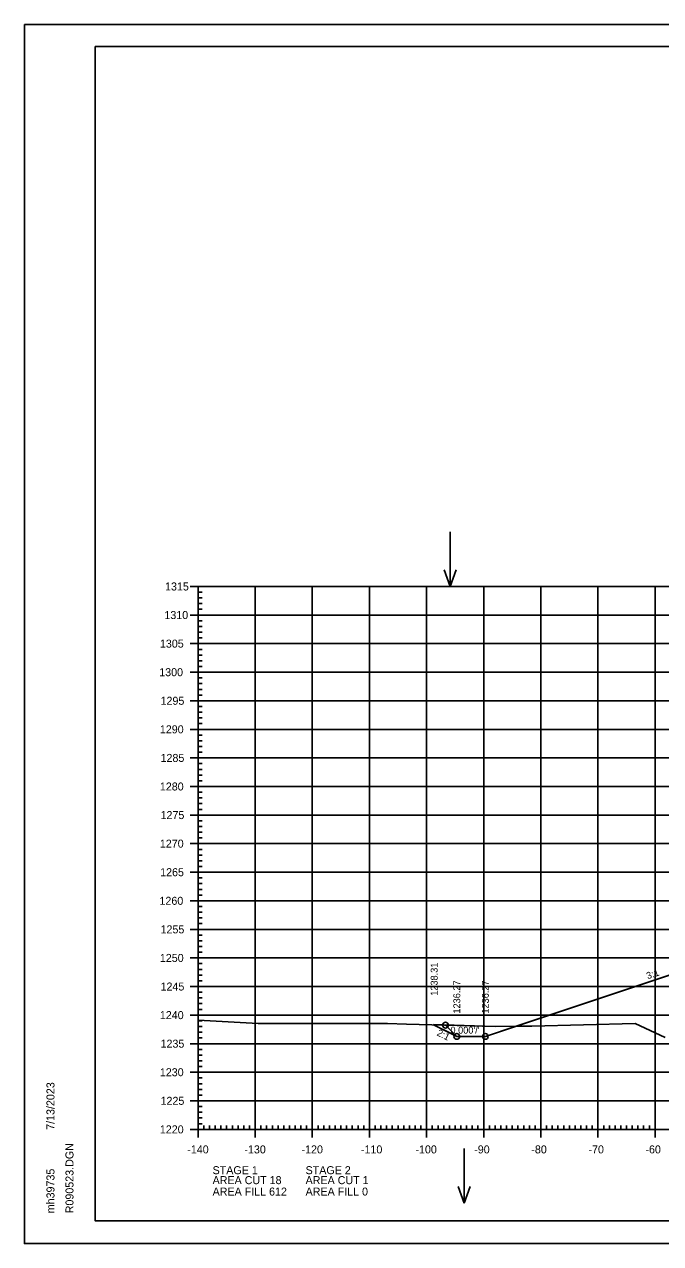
# Model space of a CAD drawing. Extents: x 1406028 to 1412453, y 321733 to 325986.
# Drawn here: x 1406419.5 to 1406530.9, y 324492.7 to 324706.1 of the extents above; entities that cross this region are included whole.
import ezdxf

# ---------------------------------------------------------------- set-up
doc = ezdxf.new("R2010")
doc.units = 0
for name, color, linetype in [('R_Axis', 7, 'Continuous'), ('R_Axis Annot', 7, 'Continuous'), ('R_Border', 7, 'Continuous'), ('R_Exist Surface', 7, 'Continuous'), ('R_Fin Surface', 7, 'Continuous'), ('R_Fin Surface Annot', 7, 'Continuous'), ('R_Grid', 7, 'Continuous'), ('R_No Plot', 7, 'Continuous'), ('R_Proposed Const Limits', 7, 'Continuous'), ('R_Proposed Road', 7, 'Continuous'), ('R_Water Annot', 7, 'Continuous')]:
    doc.layers.add(name, color=color, linetype=linetype)

msp = doc.modelspace()

# ---------------------------------------------------------------- linework, layer by layer
at = {"layer": 'R_Axis'}
for p, q in [((1406448.49, 324607.71), (1406451.29, 324607.71)), ((1406449.89, 324512.71), (1406449.89, 324607.71)), ((1406449.89, 324606.71), (1406450.59, 324606.71)), ((1406449.89, 324605.71), (1406450.59, 324605.71)), ((1406449.89, 324604.71), (1406450.59, 324604.71)), ((1406448.49, 324602.71), (1406451.29, 324602.71)), ((1406449.89, 324603.71), (1406450.59, 324603.71)), ((1406449.89, 324601.71), (1406450.59, 324601.71)), ((1406449.89, 324600.71), (1406450.59, 324600.71)), ((1406449.89, 324599.71), (1406450.59, 324599.71)), ((1406448.49, 324597.71), (1406451.29, 324597.71)), ((1406449.89, 324598.71), (1406450.59, 324598.71)), ((1406449.89, 324596.71), (1406450.59, 324596.71)), ((1406449.89, 324595.71), (1406450.59, 324595.71)), ((1406449.89, 324594.71), (1406450.59, 324594.71)), ((1406449.89, 324593.71), (1406450.59, 324593.71)), ((1406448.49, 324592.71), (1406451.29, 324592.71)), ((1406449.89, 324591.71), (1406450.59, 324591.71)), ((1406449.89, 324590.71), (1406450.59, 324590.71)), ((1406449.89, 324589.71), (1406450.59, 324589.71)), ((1406448.49, 324587.71), (1406451.29, 324587.71)), ((1406449.89, 324588.71), (1406450.59, 324588.71)), ((1406449.89, 324586.71), (1406450.59, 324586.71)), ((1406449.89, 324585.71), (1406450.59, 324585.71)), ((1406449.89, 324584.71), (1406450.59, 324584.71)), ((1406448.49, 324582.71), (1406451.29, 324582.71)), ((1406449.89, 324583.71), (1406450.59, 324583.71)), ((1406449.89, 324581.71), (1406450.59, 324581.71)), ((1406449.89, 324580.71), (1406450.59, 324580.71)), ((1406449.89, 324579.71), (1406450.59, 324579.71)), ((1406449.89, 324578.71), (1406450.59, 324578.71)), ((1406448.49, 324577.71), (1406451.29, 324577.71)), ((1406449.89, 324576.71), (1406450.59, 324576.71)), ((1406449.89, 324575.71), (1406450.59, 324575.71)), ((1406449.89, 324574.71), (1406450.59, 324574.71)), ((1406448.49, 324572.71), (1406451.29, 324572.71)), ((1406449.89, 324573.71), (1406450.59, 324573.71)), ((1406449.89, 324571.71), (1406450.59, 324571.71)), ((1406449.89, 324570.71), (1406450.59, 324570.71)), ((1406449.89, 324569.71), (1406450.59, 324569.71)), ((1406448.49, 324567.71), (1406451.29, 324567.71)), ((1406449.89, 324568.71), (1406450.59, 324568.71)), ((1406449.89, 324566.71), (1406450.59, 324566.71)), ((1406449.89, 324565.71), (1406450.59, 324565.71)), ((1406449.89, 324564.71), (1406450.59, 324564.71)), ((1406449.89, 324563.71), (1406450.59, 324563.71)), ((1406448.49, 324562.71), (1406451.29, 324562.71)), ((1406449.89, 324561.71), (1406450.59, 324561.71)), ((1406449.89, 324560.71), (1406450.59, 324560.71)), ((1406449.89, 324559.71), (1406450.59, 324559.71)), ((1406448.49, 324557.71), (1406451.29, 324557.71)), ((1406449.89, 324558.71), (1406450.59, 324558.71)), ((1406449.89, 324556.71), (1406450.59, 324556.71)), ((1406449.89, 324555.71), (1406450.59, 324555.71)), ((1406448.49, 324552.71), (1406451.29, 324552.71)), ((1406449.89, 324554.71), (1406450.59, 324554.71)), ((1406449.89, 324553.71), (1406450.59, 324553.71)), ((1406449.89, 324551.71), (1406450.59, 324551.71)), ((1406449.89, 324550.71), (1406450.59, 324550.71)), ((1406449.89, 324549.71), (1406450.59, 324549.71)), ((1406449.89, 324548.71), (1406450.59, 324548.71)), ((1406448.49, 324547.71), (1406451.29, 324547.71)), ((1406449.89, 324546.71), (1406450.59, 324546.71)), ((1406449.89, 324545.71), (1406450.59, 324545.71)), ((1406449.89, 324544.71), (1406450.59, 324544.71)), ((1406448.49, 324542.71), (1406451.29, 324542.71)), ((1406449.89, 324543.71), (1406450.59, 324543.71)), ((1406449.89, 324541.71), (1406450.59, 324541.71)), ((1406449.89, 324540.71), (1406450.59, 324540.71)), ((1406448.49, 324537.71), (1406451.29, 324537.71)), ((1406449.89, 324539.71), (1406450.59, 324539.71)), ((1406449.89, 324538.71), (1406450.59, 324538.71)), ((1406449.89, 324536.71), (1406450.59, 324536.71)), ((1406449.89, 324535.71), (1406450.59, 324535.71)), ((1406449.89, 324534.71), (1406450.59, 324534.71)), ((1406449.89, 324533.71), (1406450.59, 324533.71)), ((1406448.49, 324532.71), (1406451.29, 324532.71)), ((1406449.89, 324531.71), (1406450.59, 324531.71)), ((1406449.89, 324530.71), (1406450.59, 324530.71)), ((1406449.89, 324529.71), (1406450.59, 324529.71)), ((1406448.49, 324527.71), (1406451.29, 324527.71)), ((1406449.89, 324528.71), (1406450.59, 324528.71)), ((1406449.89, 324526.71), (1406450.59, 324526.71)), ((1406449.89, 324525.71), (1406450.59, 324525.71)), ((1406449.89, 324524.71), (1406450.59, 324524.71)), ((1406449.89, 324523.71), (1406450.59, 324523.71)), ((1406448.49, 324522.71), (1406451.29, 324522.71)), ((1406449.89, 324521.71), (1406450.59, 324521.71)), ((1406449.89, 324520.71), (1406450.59, 324520.71)), ((1406449.89, 324519.71), (1406450.59, 324519.71)), ((1406449.89, 324518.71), (1406450.59, 324518.71)), ((1406448.49, 324517.71), (1406451.29, 324517.71)), ((1406449.89, 324516.71), (1406450.59, 324516.71)), ((1406449.89, 324515.71), (1406450.59, 324515.71)), ((1406449.89, 324514.71), (1406450.59, 324514.71)), ((1406448.49, 324512.71), (1406451.29, 324512.71)), ((1406449.89, 324511.31), (1406449.89, 324514.11)), ((1406449.89, 324513.71), (1406450.59, 324513.71)), ((1406449.89, 324512.71), (1406729.89, 324512.71)), ((1406450.89, 324512.71), (1406450.89, 324513.41)), ((1406451.89, 324512.71), (1406451.89, 324513.41)), ((1406452.89, 324512.71), (1406452.89, 324513.41)), ((1406453.89, 324512.71), (1406453.89, 324513.41)), ((1406454.89, 324512.71), (1406454.89, 324513.41)), ((1406455.89, 324512.71), (1406455.89, 324513.41)), ((1406456.89, 324512.71), (1406456.89, 324513.41)), ((1406457.89, 324512.71), (1406457.89, 324513.41)), ((1406458.89, 324512.71), (1406458.89, 324513.41)), ((1406459.89, 324511.31), (1406459.89, 324514.11)), ((1406460.89, 324512.71), (1406460.89, 324513.41)), ((1406461.89, 324512.71), (1406461.89, 324513.41)), ((1406462.89, 324512.71), (1406462.89, 324513.41)), ((1406463.89, 324512.71), (1406463.89, 324513.41)), ((1406464.89, 324512.71), (1406464.89, 324513.41)), ((1406465.89, 324512.71), (1406465.89, 324513.41)), ((1406466.89, 324512.71), (1406466.89, 324513.41)), ((1406467.89, 324512.71), (1406467.89, 324513.41)), ((1406468.89, 324512.71), (1406468.89, 324513.41)), ((1406469.89, 324511.31), (1406469.89, 324514.11)), ((1406470.89, 324512.71), (1406470.89, 324513.41)), ((1406471.89, 324512.71), (1406471.89, 324513.41)), ((1406472.89, 324512.71), (1406472.89, 324513.41)), ((1406473.89, 324512.71), (1406473.89, 324513.41)), ((1406474.89, 324512.71), (1406474.89, 324513.41)), ((1406475.89, 324512.71), (1406475.89, 324513.41)), ((1406476.89, 324512.71), (1406476.89, 324513.41)), ((1406477.89, 324512.71), (1406477.89, 324513.41)), ((1406478.89, 324512.71), (1406478.89, 324513.41)), ((1406479.89, 324511.31), (1406479.89, 324514.11)), ((1406480.89, 324512.71), (1406480.89, 324513.41)), ((1406481.89, 324512.71), (1406481.89, 324513.41)), ((1406482.89, 324512.71), (1406482.89, 324513.41)), ((1406483.89, 324512.71), (1406483.89, 324513.41)), ((1406484.89, 324512.71), (1406484.89, 324513.41)), ((1406485.89, 324512.71), (1406485.89, 324513.41)), ((1406486.89, 324512.71), (1406486.89, 324513.41)), ((1406487.89, 324512.71), (1406487.89, 324513.41)), ((1406488.89, 324512.71), (1406488.89, 324513.41)), ((1406489.89, 324511.31), (1406489.89, 324514.11)), ((1406490.89, 324512.71), (1406490.89, 324513.41)), ((1406491.89, 324512.71), (1406491.89, 324513.41)), ((1406492.89, 324512.71), (1406492.89, 324513.41)), ((1406493.89, 324512.71), (1406493.89, 324513.41)), ((1406494.89, 324512.71), (1406494.89, 324513.41)), ((1406495.89, 324512.71), (1406495.89, 324513.41)), ((1406496.89, 324512.71), (1406496.89, 324513.41)), ((1406497.89, 324512.71), (1406497.89, 324513.41)), ((1406498.89, 324512.71), (1406498.89, 324513.41)), ((1406499.89, 324511.31), (1406499.89, 324514.11)), ((1406500.89, 324512.71), (1406500.89, 324513.41)), ((1406501.89, 324512.71), (1406501.89, 324513.41)), ((1406502.89, 324512.71), (1406502.89, 324513.41)), ((1406503.89, 324512.71), (1406503.89, 324513.41)), ((1406504.89, 324512.71), (1406504.89, 324513.41)), ((1406505.89, 324512.71), (1406505.89, 324513.41)), ((1406506.89, 324512.71), (1406506.89, 324513.41)), ((1406507.89, 324512.71), (1406507.89, 324513.41)), ((1406508.89, 324512.71), (1406508.89, 324513.41)), ((1406509.89, 324511.31), (1406509.89, 324514.11)), ((1406510.89, 324512.71), (1406510.89, 324513.41)), ((1406511.89, 324512.71), (1406511.89, 324513.41)), ((1406512.89, 324512.71), (1406512.89, 324513.41)), ((1406513.89, 324512.71), (1406513.89, 324513.41)), ((1406514.89, 324512.71), (1406514.89, 324513.41)), ((1406515.89, 324512.71), (1406515.89, 324513.41)), ((1406516.89, 324512.71), (1406516.89, 324513.41)), ((1406517.89, 324512.71), (1406517.89, 324513.41)), ((1406518.89, 324512.71), (1406518.89, 324513.41)), ((1406519.89, 324511.31), (1406519.89, 324514.11)), ((1406520.89, 324512.71), (1406520.89, 324513.41)), ((1406521.89, 324512.71), (1406521.89, 324513.41)), ((1406522.89, 324512.71), (1406522.89, 324513.41)), ((1406523.89, 324512.71), (1406523.89, 324513.41)), ((1406524.89, 324512.71), (1406524.89, 324513.41)), ((1406525.89, 324512.71), (1406525.89, 324513.41)), ((1406526.89, 324512.71), (1406526.89, 324513.41)), ((1406527.89, 324512.71), (1406527.89, 324513.41)), ((1406528.89, 324512.71), (1406528.89, 324513.41)), ((1406529.89, 324511.31), (1406529.89, 324514.11))]:
    msp.add_line(p, q, dxfattribs=at)
at = {"layer": 'R_Border'}
for p, q in [((1406431.89, 324702.17), (1406748.07, 324702.17)), ((1406431.89, 324496.71), (1406431.89, 324702.17)), ((1406431.89, 324496.71), (1406431.89, 324496.71)), ((1406748.07, 324496.71), (1406431.89, 324496.71))]:
    msp.add_line(p, q, dxfattribs=at)
at = {"layer": 'R_Exist Surface'}
msp.add_lwpolyline([(1406449.89, 324531.84), (1406460.42, 324531.22), (1406481.71, 324531.24), (1406483.06, 324531.24), (1406486.36, 324531.15), (1406501.88, 324530.7), (1406508.3, 324530.8), (1406526.38, 324531.23), (1406531.65, 324528.77)], dxfattribs=at)
at = {"layer": 'R_Fin Surface'}
msp.add_line((1406495.19, 324528.97), (1406491.11, 324531.01), dxfattribs=at)
msp.add_lwpolyline([(1406491.11, 324531.01), (1406494.49, 324529.32), (1406495.18, 324528.97), (1406498.92, 324528.97), (1406500.18, 324528.97), (1406545.18, 324543.97)], dxfattribs=at)
at = {"layer": 'R_Grid'}
for p, q in [((1406449.89, 324607.71), (1406729.89, 324607.71)), ((1406449.89, 324512.71), (1406449.89, 324607.71)), ((1406459.89, 324512.71), (1406459.89, 324607.71)), ((1406469.89, 324512.71), (1406469.89, 324607.71)), ((1406479.89, 324512.71), (1406479.89, 324607.71)), ((1406489.89, 324512.71), (1406489.89, 324607.71)), ((1406499.89, 324512.71), (1406499.89, 324607.71)), ((1406509.89, 324512.71), (1406509.89, 324607.71)), ((1406519.89, 324512.71), (1406519.89, 324607.71)), ((1406529.89, 324512.71), (1406529.89, 324607.71)), ((1406449.89, 324602.71), (1406729.89, 324602.71)), ((1406449.89, 324597.71), (1406729.89, 324597.71)), ((1406449.89, 324592.71), (1406729.89, 324592.71)), ((1406449.89, 324587.71), (1406729.89, 324587.71)), ((1406449.89, 324582.71), (1406729.89, 324582.71)), ((1406449.89, 324577.71), (1406729.89, 324577.71)), ((1406449.89, 324572.71), (1406729.89, 324572.71)), ((1406449.89, 324567.71), (1406729.89, 324567.71)), ((1406449.89, 324562.71), (1406729.89, 324562.71)), ((1406449.89, 324557.71), (1406729.89, 324557.71)), ((1406449.89, 324552.71), (1406729.89, 324552.71)), ((1406449.89, 324547.71), (1406729.89, 324547.71)), ((1406449.89, 324542.71), (1406729.89, 324542.71)), ((1406449.89, 324537.71), (1406729.89, 324537.71)), ((1406449.89, 324532.71), (1406729.89, 324532.71)), ((1406449.89, 324527.71), (1406729.89, 324527.71)), ((1406449.89, 324522.71), (1406729.89, 324522.71)), ((1406449.89, 324517.71), (1406729.89, 324517.71)), ((1406449.89, 324512.71), (1406729.89, 324512.71))]:
    msp.add_line(p, q, dxfattribs=at)
at = {"layer": 'R_No Plot'}
for p, q in [((1406419.49, 324706.06), (1406752.82, 324706.06)), ((1406419.49, 324492.73), (1406752.82, 324492.73))]:
    msp.add_line(p, q, dxfattribs=at)
for points in [[(1406419.48, 324706.06), (1406752.82, 324706.06), (1406752.82, 324492.72), (1406419.48, 324492.72)], [(1406665.81, 324702.17), (1406685.43, 324702.17), (1406685.43, 324692.29), (1406701.54, 324692.29), (1406724.74, 324692.29), (1406724.74, 324667.95), (1406748.07, 324667.95), (1406748.07, 324496.71), (1406431.89, 324496.71), (1406431.89, 324702.17)], [(1406491.11, 324531.01), (1406491.11, 324531.06), (1406501.88, 324530.7), (1406505.55, 324530.76), (1406500.19, 324528.97), (1406498.25, 324528.97), (1406495.2, 324528.97), (1406494.19, 324529.47)]]:
    msp.add_lwpolyline(points, close=True, dxfattribs=at)
msp.add_lwpolyline([(1406537.41, 324541.37), (1406505.55, 324530.76), (1406508.3, 324530.8), (1406526.38, 324531.23), (1406531.65, 324528.77)], dxfattribs=at)
for centre in [(1406493.2, 324530.95), (1406495.18, 324528.97), (1406500.18, 324528.97)]:
    msp.add_circle(centre, 0.5, dxfattribs=at)
at = {"layer": 'R_Proposed Const Limits'}
msp.add_lwpolyline([(1406500.18, 324528.97), (1406495.18, 324528.97), (1406493.2, 324530.95)], dxfattribs=at)
at = {"layer": 'R_Proposed Road'}
msp.add_lwpolyline([(1406559.89, 324548.88), (1406500.18, 324528.97)], dxfattribs=at)
at = {"layer": 'R_Water Annot'}
for p, q in [((1406494, 324617.28), (1406494, 324607.71)), ((1406494, 324607.71), (1406492.94, 324610.64)), ((1406494, 324607.71), (1406495.07, 324610.64)), ((1406496.46, 324509.36), (1406496.46, 324499.79)), ((1406496.46, 324499.79), (1406495.4, 324502.72)), ((1406496.46, 324499.79), (1406497.53, 324502.72))]:
    msp.add_line(p, q, dxfattribs=at)

# ---------------------------------------------------------------- texts
at = {"layer": 'R_Axis Annot'}
for s, p in [('1315', (1406444.11, 324607.01)), ('1310', (1406443.99, 324602.01)), ('1305', (1406443.21, 324597.01)), ('1300', (1406443.09, 324592.01)), ('1295', (1406443.32, 324587.01)), ('1290', (1406443.2, 324582.01)), ('1285', (1406443.32, 324577.01)), ('1280', (1406443.2, 324572.01)), ('1275', (1406443.32, 324567.01)), ('1270', (1406443.2, 324562.01)), ('1265', (1406443.25, 324557.01)), ('1260', (1406443.13, 324552.01)), ('1255', (1406443.32, 324547.01)), ('1250', (1406443.2, 324542.01)), ('1245', (1406443.32, 324537.01)), ('1240', (1406443.2, 324532.01)), ('1235', (1406443.32, 324527.01)), ('1230', (1406443.2, 324522.01)), ('1225', (1406443.32, 324517.01)), ('1220', (1406443.2, 324512.01)), ('-140', (1406448, 324508.51)), ('-130', (1406458, 324508.51)), ('-120', (1406468, 324508.51)), ('-110', (1406478.4, 324508.51)), ('-100', (1406487.94, 324508.51)), ('-90', (1406498.23, 324508.51)), ('-80', (1406508.23, 324508.51)), ('-70', (1406518.23, 324508.51)), ('-60', (1406528.2, 324508.51)), ('STAGE 1', (1406452.43, 324504.87)), ('STAGE 2', (1406468.71, 324504.87)), ('AREA CUT 18', (1406452.43, 324503.13)), ('AREA CUT 1', (1406468.71, 324503.13)), ('AREA FILL 612', (1406452.43, 324501.13)), ('AREA FILL 0', (1406468.71, 324501.13))]:
    msp.add_text(s, height=1.4, dxfattribs=at).set_placement(p)
at = {"layer": 'R_Border'}
for s, p in [('7/13/2023', (1406424.75, 324512.63)), ('R090523.DGN', (1406428.08, 324498.03)), ('mh39735', (1406424.75, 324498.03))]:
    msp.add_text(s, height=1.4, rotation=90, dxfattribs=at).set_placement(p)
at = {"layer": 'R_Fin Surface Annot'}
for s, rotation, p in [('1238.31', 90, (1406491.82, 324536.09)), ('3:1', 18.4333, (1406528.6, 324538.97)), ('1236.27', 90, (1406495.78, 324532.97)), ('1236.27', 90, (1406500.78, 324532.97)), ('2:1', 333.43, (1406491.58, 324529.22)), ("0.000'/'", 0, (1406494.07, 324529.47))]:
    msp.add_text(s, height=1.2, rotation=rotation, dxfattribs=at).set_placement(p)
at = {"layer": 'R_No Plot'}
for p in [(1406460.38, 324531.17), (1406483.02, 324531.19), (1406501.83, 324530.65), (1406526.34, 324531.18)]:
    msp.add_text('+', height=0.1, dxfattribs=at).set_placement(p)

doc.saveas('drawing.dxf')
